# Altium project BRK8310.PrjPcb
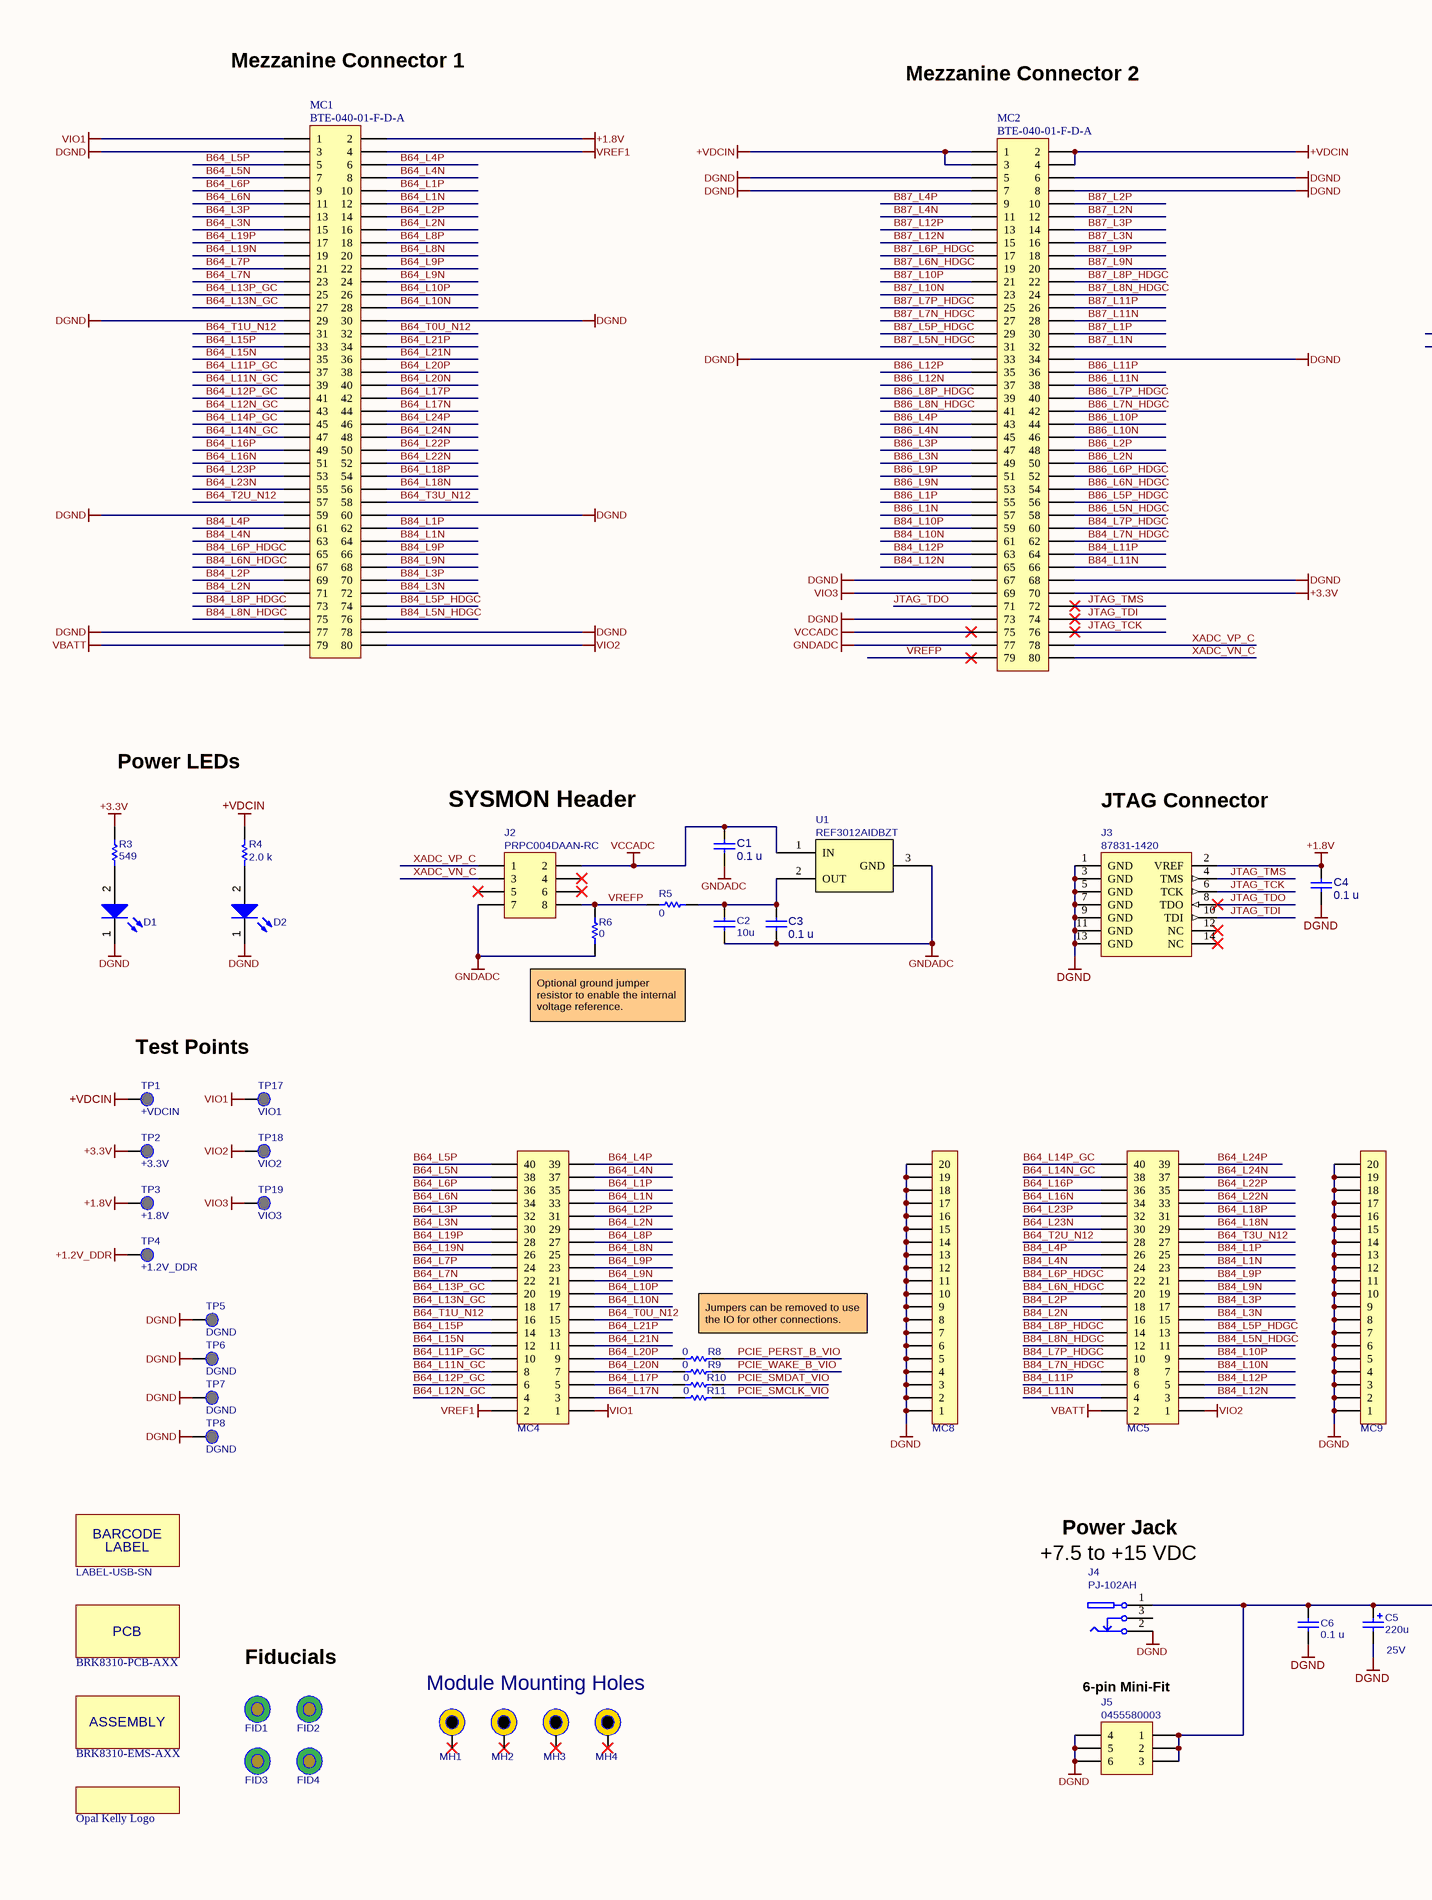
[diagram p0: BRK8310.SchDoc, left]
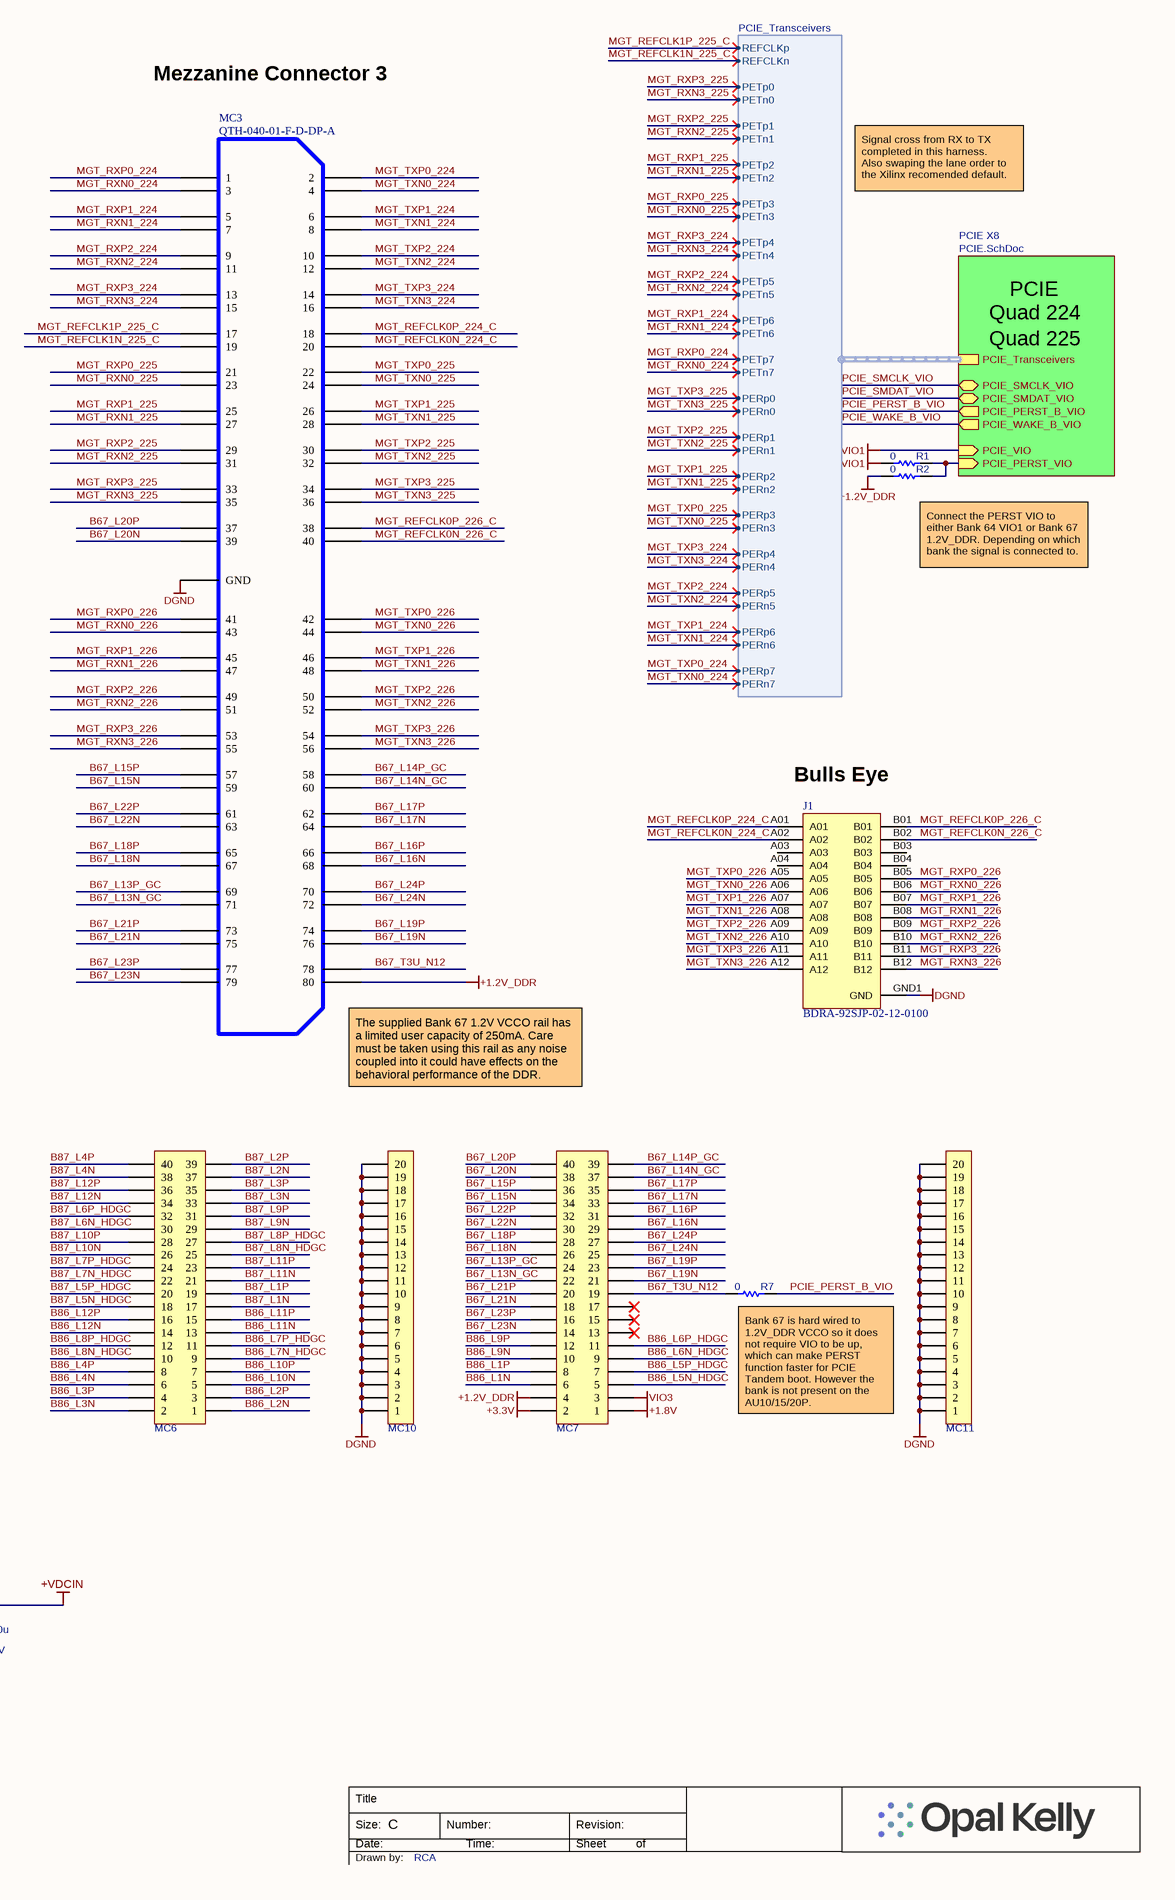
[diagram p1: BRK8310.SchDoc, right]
BOM_Revision: 01; Part_Number: BRK8310; PCB_Revision: A
2 sheets, 122 parts. Net scope: hierarchical (ports join the sheet entries above them; power ports are global).
Board file: BRK8310.PcbDoc
Sheets:
  BRK8310.SchDoc
    PCIE X8 = PCIE.SchDoc

## Sheet BRK8310.SchDoc: BRK8310 PCB
size C; Author: Ray Anderson; Organization: Opal Kelly; Address1: 13500 SW 72nd Ave, STE 100; Address2: Portland, OR 97223; Address3: 217.391.3724; Address4: http://www.opalkelly.com; DocumentNumber: 1; Revision: 1; SheetNumber: 1; SheetTotal: 2

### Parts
*  Opal Kelly Logo  [okLogo-23x5-2021]
ASSY1  BRK8310-EMS-AXX  (mechanical)
C1  value 0.1 u  [CAPC1005X06A]  (hidden comment: C0402C104K8PACTU)
C2  value 10u  [CAPC1005X06A]  (hidden comment: GRM155C80J106ME11D)
C3  value 0.1 u  [CAPC1005X06A]  (hidden comment: C0402C104K8PACTU)
C4  value 0.1 u  [CAPC1005X06A]  (hidden comment: C0402C104K8PACTU)
C5  value 220u  Voltage: 25V  [CAPAE9083X70N]  (hidden comment: EEE-FK1E221P)
C6  value 0.1 u  [CAPC1005X06A]  (hidden comment: TMK105BJ104KV-F)
D1  +3.3VDD  [CD1608-0603-PIN1-CATHODE]  (value not drawn)
D2  +VDC  [CD1608-0603-PIN1-CATHODE]  (value not drawn)
FID1  FIDUCIAL  [FID1MM/2MM-SS]  (value not drawn)
FID2  FIDUCIAL  [FID1MM/2MM-SS]  (value not drawn)
FID3  FIDUCIAL  [FID1MM/2MM-SS]  (value not drawn)
FID4  FIDUCIAL  [FID1MM/2MM-SS]  (value not drawn)
J1  BDRA-92SJP-02-12-0100  [SAMTEC_BDRA-92SJP-02-12-0100]
J2  PRPC004DAAN-RC  [HDR2X4]
J3  87831-1420  [XILINX-JTAG]
J4  PJ-102AH  [CUI-PJ102A]
J5  0455580003  [0455580003]
LABEL1  LABEL-USB-SN  (mechanical)
MC1  BTE-040-01-F-D-A  [BTE-040]
MC2  BTE-040-01-F-D-A  [BTE-040]
MC3  QTH-040-01-F-D-DP-A  [QTH-040-01-X-D-DP-A]
MC4  0877584016  [HDR2X20-2MM]  (value not drawn)
MC5  0877584016  [HDR2X20-2MM]  (value not drawn)
MC6  0877584016  [HDR2X20-2MM]  (value not drawn)
MC7  0877584016  [HDR2X20-2MM]  (value not drawn)
MC8  Header, 20-Pin, Single Row  [HDR1X20-2MM]  (value not drawn)
MC9  Header, 20-Pin, Single Row  [HDR1X20-2MM]  (value not drawn)
MC10  Header, 20-Pin, Single Row  [HDR1X20-2MM]  (value not drawn)
MC11  Header, 20-Pin, Single Row  [HDR1X20-2MM]  (value not drawn)
MH1  MTG  [MTG-3.2/6.5-PTH]  (value not drawn)
MH2  MTG  [MTG-3.2/6.5-PTH]  (value not drawn)
MH3  MTG  [MTG-3.2/6.5-PTH]  (value not drawn)
MH4  MTG  [MTG-3.2/6.5-PTH]  (value not drawn)
PCB1  BRK8310-PCB-AXX  (mechanical)
R1  value 0  [RESC1608N]  (hidden comment: CRCW06030000Z0EA)
R2  value 0  [RESC1608N]  (hidden comment: CRCW06030000Z0EA)
R3  value 549  [RESC1005X06A]  (hidden comment: CRCW0402549RFKED)
R4  value 2.0 k  [RESC1005X06A]  (hidden comment: CRCW04022K00FKED)
R5  value 0  [RESC1608N]  (hidden comment: CRCW06030000Z0EA)
R6  value 0  [RESC1608N]  (hidden comment: CRCW06030000Z0EA)
R7  value 0  [RESC1608N]  (hidden comment: CRCW06030000Z0EA)
R8  value 0  [RESC1608N]  (hidden comment: CRCW06030000Z0EA)
R9  value 0  [RESC1608N]  (hidden comment: CRCW06030000Z0EA)
R10  value 0  [RESC1608N]  (hidden comment: CRCW06030000Z0EA)
R11  value 0  [RESC1608N]  (hidden comment: CRCW06030000Z0EA)
TP1  +VDCIN  [TP-PTH-65/100]
TP2  +3.3V  [TP-PTH-65/100]
TP3  +1.8V  [TP-PTH-65/100]
TP4  +1.2V_DDR  [TP-PTH-65/100]
TP5  DGND  [TP-PTH-65/100]
TP6  DGND  [TP-PTH-65/100]
TP7  DGND  [TP-PTH-65/100]
TP8  DGND  [TP-PTH-65/100]
TP17  VIO1  [TP-PTH-65/100]
TP18  VIO2  [TP-PTH-65/100]
TP19  VIO3  [TP-PTH-65/100]
U1  REF3012AIDBZT  [SOT23-95P240X110]

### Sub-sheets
PCIE X8 = PCIE.SchDoc: PCIE_Transceivers (harness PCIE_Transceivers), PCIE_SMCLK_VIO (bidir), PCIE_WAKE_B_VIO (out), PCIE_SMDAT_VIO (bidir), PCIE_PERST_B_VIO (out), PCIE_VIO (in), PCIE_PERST_VIO (in)

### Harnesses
PCIE_Transceivers: PETn3, PETp3, PERn3, PERp3, PETn2, PETp2, PERn2, PERp2, PETn1, PETp1, PERn1, PERp1, PETn0, PETp0, PERn0, PERp0, PETn4, PETp4, PERn4, PERp4, PETn5, PETp5, PERn5, PERp5, PETn6, PETp6, PERn6, PERp6, PETn7, PETp7, PERn7, PERp7, REFCLKn, REFCLKp

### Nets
+1.2V_DDR: MC3.80 MC7.4 R2.2 TP4.1(PIN)
+1.8V: C4.1 J3.2(VREF) MC1.2 MC7.1 TP3.1(PIN)
+3.3V: MC2.70 MC7.2 R3.2 TP2.1(PIN)
+VDCIN: C5.1 C6.2 J4.1 J5.1 J5.2 J5.3 MC2.1 MC2.2 MC2.3 MC2.4 R4.2 TP1.1(PIN)
DGND: C4.2 C5.2 C6.1 D1.1(K) D2.1(K) J1.GND1(GND) J3.1(GND) J3.3(GND) J3.5(GND) J3.7(GND) J3.9(GND) J3.11(GND) J3.13(GND) J4.2 J5.4 J5.5 J5.6 MC1.3 MC1.29 MC1.30 MC1.59 MC1.60 MC1.77 MC1.78 MC2.5 MC2.6 MC2.7 MC2.8 MC2.33 MC2.34 MC2.67 MC2.68 MC2.73 MC3.0(GND) MC8.1 MC8.2 MC8.3 MC8.4 MC8.5 MC8.6 MC8.7 MC8.8 MC8.9 MC8.10 MC8.11 MC8.12 MC8.13 MC8.14 MC8.15 MC8.16 MC8.17 MC8.18 MC8.19 MC8.20 MC9.1 MC9.2 MC9.3 MC9.4 MC9.5 MC9.6 MC9.7 MC9.8 MC9.9 MC9.10 MC9.11 MC9.12 MC9.13 MC9.14 MC9.15 MC9.16 MC9.17 MC9.18 MC9.19 MC9.20 MC10.1 MC10.2 MC10.3 MC10.4 MC10.5 MC10.6 MC10.7 MC10.8 MC10.9 MC10.10 MC10.11 MC10.12 MC10.13 MC10.14 MC10.15 MC10.16 MC10.17 MC10.18 MC10.19 MC10.20 MC11.1 MC11.2 MC11.3 MC11.4 MC11.5 MC11.6 MC11.7 MC11.8 MC11.9 MC11.10 MC11.11 MC11.12 MC11.13 MC11.14 MC11.15 MC11.16 MC11.17 MC11.18 MC11.19 MC11.20 TP5.1(PIN) TP6.1(PIN) TP7.1(PIN) TP8.1(PIN)
GNDADC: C1.2 C2.1 C3.2 J2.7 MC2.77 R6.1 U1.3(GND)
VBATT: MC1.79 MC5.2
VCCADC: C1.1 J2.2 MC2.75 U1.1(IN)
VIO1: MC1.1 MC4.1 R1.2 TP17.1(PIN) ; sheet PCIE X8/PCIE_VIO
VIO2: MC1.80 MC5.1 TP18.1(PIN)
VIO3: MC2.69 MC7.3 TP19.1(PIN)
VREF1: MC1.4 MC4.2
B64_L1N: MC1.12 MC4.33
B64_L1P: MC1.10 MC4.35
B64_L2N: MC1.16 MC4.29
B64_L2P: MC1.14 MC4.31
B64_L3N: MC1.15 MC4.30
B64_L3P: MC1.13 MC4.32
B64_L4N: MC1.8 MC4.37
B64_L4P: MC1.6 MC4.39
B64_L5N: MC1.7 MC4.38
B64_L5P: MC1.5 MC4.40
B64_L6N: MC1.11 MC4.34
B64_L6P: MC1.9 MC4.36
B64_L7N: MC1.23 MC4.22
B64_L7P: MC1.21 MC4.24
B64_L8N: MC1.20 MC4.25
B64_L8P: MC1.18 MC4.27
B64_L9N: MC1.24 MC4.21
B64_L9P: MC1.22 MC4.23
B64_L10N: MC1.28 MC4.17
B64_L10P: MC1.26 MC4.19
B64_L11N_GC: MC1.39 MC4.8
B64_L11P_GC: MC1.37 MC4.10
B64_L12N_GC: MC1.43 MC4.4
B64_L12P_GC: MC1.41 MC4.6
B64_L13N_GC: MC1.27 MC4.18
B64_L13P_GC: MC1.25 MC4.20
B64_L14N_GC: MC1.47 MC5.38
B64_L14P_GC: MC1.45 MC5.40
B64_L15N: MC1.35 MC4.12
B64_L15P: MC1.33 MC4.14
B64_L16N: MC1.51 MC5.34
B64_L16P: MC1.49 MC5.36
B64_L17N: MC1.44 MC4.3 R11.2
B64_L17P: MC1.42 MC4.5 R10.2
B64_L18N: MC1.56 MC5.29
B64_L18P: MC1.54 MC5.31
B64_L19N: MC1.19 MC4.26
B64_L19P: MC1.17 MC4.28
B64_L20N: MC1.40 MC4.7 R9.2
B64_L20P: MC1.38 MC4.9 R8.2
B64_L21N: MC1.36 MC4.11
B64_L21P: MC1.34 MC4.13
B64_L22N: MC1.52 MC5.33
B64_L22P: MC1.50 MC5.35
B64_L23N: MC1.55 MC5.30
B64_L23P: MC1.53 MC5.32
B64_L24N: MC1.48 MC5.37
B64_L24P: MC1.46 MC5.39
B64_T0U_N12: MC1.32 MC4.15
B64_T1U_N12: MC1.31 MC4.16
B64_T2U_N12: MC1.57 MC5.28
B64_T3U_N12: MC1.58 MC5.27
B67_L13N_GC: MC3.71 MC7.22
B67_L13P_GC: MC3.69 MC7.24
B67_L14N_GC: MC3.60 MC7.37
B67_L14P_GC: MC3.58 MC7.39
B67_L15N: MC3.59 MC7.34
B67_L15P: MC3.57 MC7.36
B67_L16N: MC3.68 MC7.29
B67_L16P: MC3.66 MC7.31
B67_L17N: MC3.64 MC7.33
B67_L17P: MC3.62 MC7.35
B67_L18N: MC3.67 MC7.26
B67_L18P: MC3.65 MC7.28
B67_L19N: MC3.76 MC7.21
B67_L19P: MC3.74 MC7.23
B67_L20N: MC3.39 MC7.38
B67_L20P: MC3.37 MC7.40
B67_L21N: MC3.75 MC7.18
B67_L21P: MC3.73 MC7.20
B67_L22N: MC3.63 MC7.30
B67_L22P: MC3.61 MC7.32
B67_L23N: MC3.79 MC7.14
B67_L23P: MC3.77 MC7.16
B67_L24N: MC3.72 MC7.25
B67_L24P: MC3.70 MC7.27
B67_T3U_N12: MC3.78 MC7.19 R7.2
B84_L1N: MC1.64 MC5.23
B84_L1P: MC1.62 MC5.25
B84_L2N: MC1.71 MC5.16
B84_L2P: MC1.69 MC5.18
B84_L3N: MC1.72 MC5.15
B84_L3P: MC1.70 MC5.17
B84_L4N: MC1.63 MC5.24
B84_L4P: MC1.61 MC5.26
B84_L5N_HDGC: MC1.76 MC5.11
B84_L5P_HDGC: MC1.74 MC5.13
B84_L6N_HDGC: MC1.67 MC5.20
B84_L6P_HDGC: MC1.65 MC5.22
B84_L7N_HDGC: MC2.62 MC5.8
B84_L7P_HDGC: MC2.60 MC5.10
B84_L8N_HDGC: MC1.75 MC5.12
B84_L8P_HDGC: MC1.73 MC5.14
B84_L9N: MC1.68 MC5.19
B84_L9P: MC1.66 MC5.21
B84_L10N: MC2.61 MC5.7
B84_L10P: MC2.59 MC5.9
B84_L11N: MC2.66 MC5.4
B84_L11P: MC2.64 MC5.6
B84_L12N: MC2.65 MC5.3
B84_L12P: MC2.63 MC5.5
B86_L1N: MC2.57 MC7.6
B86_L1P: MC2.55 MC7.8
B86_L2N: MC2.50 MC6.1
B86_L2P: MC2.48 MC6.3
B86_L3N: MC2.49 MC6.2
B86_L3P: MC2.47 MC6.4
B86_L4N: MC2.45 MC6.6
B86_L4P: MC2.43 MC6.8
B86_L5N_HDGC: MC2.58 MC7.5
B86_L5P_HDGC: MC2.56 MC7.7
B86_L6N_HDGC: MC2.54 MC7.9
B86_L6P_HDGC: MC2.52 MC7.11
B86_L7N_HDGC: MC2.42 MC6.9
B86_L7P_HDGC: MC2.40 MC6.11
B86_L8N_HDGC: MC2.41 MC6.10
B86_L8P_HDGC: MC2.39 MC6.12
B86_L9N: MC2.53 MC7.10
B86_L9P: MC2.51 MC7.12
B86_L10N: MC2.46 MC6.5
B86_L10P: MC2.44 MC6.7
B86_L11N: MC2.38 MC6.13
B86_L11P: MC2.36 MC6.15
B86_L12N: MC2.37 MC6.14
B86_L12P: MC2.35 MC6.16
B87_L1N: MC2.32 MC6.17
B87_L1P: MC2.30 MC6.19
B87_L2N: MC2.12 MC6.37
B87_L2P: MC2.10 MC6.39
B87_L3N: MC2.16 MC6.33
B87_L3P: MC2.14 MC6.35
B87_L4N: MC2.11 MC6.38
B87_L4P: MC2.9 MC6.40
B87_L5N_HDGC: MC2.31 MC6.18
B87_L5P_HDGC: MC2.29 MC6.20
B87_L6N_HDGC: MC2.19 MC6.30
B87_L6P_HDGC: MC2.17 MC6.32
B87_L7N_HDGC: MC2.27 MC6.22
B87_L7P_HDGC: MC2.25 MC6.24
B87_L8N_HDGC: MC2.24 MC6.25
B87_L8P_HDGC: MC2.22 MC6.27
B87_L9N: MC2.20 MC6.29
B87_L9P: MC2.18 MC6.31
B87_L10N: MC2.23 MC6.26
B87_L10P: MC2.21 MC6.28
B87_L11N: MC2.28 MC6.21
B87_L11P: MC2.26 MC6.23
B87_L12N: MC2.15 MC6.34
B87_L12P: MC2.13 MC6.36
JTAG_TCK: J3.6(TCK) MC2.76
JTAG_TDI: J3.10(TDI) MC2.74
JTAG_TDO: J3.8(TDO) MC2.71
JTAG_TMS: J3.4(TMS) MC2.72
MGT_REFCLK0N_224_C: J1.A02 MC3.20
MGT_REFCLK0N_226_C: J1.B02 MC3.40
MGT_REFCLK0P_224_C: J1.A01 MC3.18
MGT_REFCLK0P_226_C: J1.B01 MC3.38
MGT_REFCLK1N_225_C: MC3.19 ; sheet PCIE X8/PCIE_Transceivers.REFCLKn
MGT_REFCLK1P_225_C: MC3.17 ; sheet PCIE X8/PCIE_Transceivers.REFCLKp
MGT_RXN0_224: MC3.3 ; sheet PCIE X8/PCIE_Transceivers.PETn7
MGT_RXN0_225: MC3.23 ; sheet PCIE X8/PCIE_Transceivers.PETn3
MGT_RXN0_226: J1.B06 MC3.43
MGT_RXN1_224: MC3.7 ; sheet PCIE X8/PCIE_Transceivers.PETn6
MGT_RXN1_225: MC3.27 ; sheet PCIE X8/PCIE_Transceivers.PETn2
MGT_RXN1_226: J1.B08 MC3.47
MGT_RXN2_224: MC3.11 ; sheet PCIE X8/PCIE_Transceivers.PETn5
MGT_RXN2_225: MC3.31 ; sheet PCIE X8/PCIE_Transceivers.PETn1
MGT_RXN2_226: J1.B10 MC3.51
MGT_RXN3_224: MC3.15 ; sheet PCIE X8/PCIE_Transceivers.PETn4
MGT_RXN3_225: MC3.35 ; sheet PCIE X8/PCIE_Transceivers.PETn0
MGT_RXN3_226: J1.B12 MC3.55
MGT_RXP0_224: MC3.1 ; sheet PCIE X8/PCIE_Transceivers.PETp7
MGT_RXP0_225: MC3.21 ; sheet PCIE X8/PCIE_Transceivers.PETp3
MGT_RXP0_226: J1.B05 MC3.41
MGT_RXP1_224: MC3.5 ; sheet PCIE X8/PCIE_Transceivers.PETp6
MGT_RXP1_225: MC3.25 ; sheet PCIE X8/PCIE_Transceivers.PETp2
MGT_RXP1_226: J1.B07 MC3.45
MGT_RXP2_224: MC3.9 ; sheet PCIE X8/PCIE_Transceivers.PETp5
MGT_RXP2_225: MC3.29 ; sheet PCIE X8/PCIE_Transceivers.PETp1
MGT_RXP2_226: J1.B09 MC3.49
MGT_RXP3_224: MC3.13 ; sheet PCIE X8/PCIE_Transceivers.PETp4
MGT_RXP3_225: MC3.33 ; sheet PCIE X8/PCIE_Transceivers.PETp0
MGT_RXP3_226: J1.B11 MC3.53
MGT_TXN0_224: MC3.4 ; sheet PCIE X8/PCIE_Transceivers.PERn7
MGT_TXN0_225: MC3.24 ; sheet PCIE X8/PCIE_Transceivers.PERn3
MGT_TXN0_226: J1.A06 MC3.44
MGT_TXN1_224: MC3.8 ; sheet PCIE X8/PCIE_Transceivers.PERn6
MGT_TXN1_225: MC3.28 ; sheet PCIE X8/PCIE_Transceivers.PERn2
MGT_TXN1_226: J1.A08 MC3.48
MGT_TXN2_224: MC3.12 ; sheet PCIE X8/PCIE_Transceivers.PERn5
MGT_TXN2_225: MC3.32 ; sheet PCIE X8/PCIE_Transceivers.PERn1
MGT_TXN2_226: J1.A10 MC3.52
MGT_TXN3_224: MC3.16 ; sheet PCIE X8/PCIE_Transceivers.PERn4
MGT_TXN3_225: MC3.36 ; sheet PCIE X8/PCIE_Transceivers.PERn0
MGT_TXN3_226: J1.A12 MC3.56
MGT_TXP0_224: MC3.2 ; sheet PCIE X8/PCIE_Transceivers.PERp7
MGT_TXP0_225: MC3.22 ; sheet PCIE X8/PCIE_Transceivers.PERp3
MGT_TXP0_226: J1.A05 MC3.42
MGT_TXP1_224: MC3.6 ; sheet PCIE X8/PCIE_Transceivers.PERp6
MGT_TXP1_225: MC3.26 ; sheet PCIE X8/PCIE_Transceivers.PERp2
MGT_TXP1_226: J1.A07 MC3.46
MGT_TXP2_224: MC3.10 ; sheet PCIE X8/PCIE_Transceivers.PERp5
MGT_TXP2_225: MC3.30 ; sheet PCIE X8/PCIE_Transceivers.PERp1
MGT_TXP2_226: J1.A09 MC3.50
MGT_TXP3_224: MC3.14 ; sheet PCIE X8/PCIE_Transceivers.PERp4
MGT_TXP3_225: MC3.34 ; sheet PCIE X8/PCIE_Transceivers.PERp0
MGT_TXP3_226: J1.A11 MC3.54
PCIE_PERST_B_VIO: R7.1 R8.1 ; sheet PCIE X8/PCIE_PERST_B_VIO
PCIE_SMCLK_VIO: R11.1 ; sheet PCIE X8/PCIE_SMCLK_VIO
PCIE_SMDAT_VIO: R10.1 ; sheet PCIE X8/PCIE_SMDAT_VIO
PCIE_WAKE_B_VIO: R9.1 ; sheet PCIE X8/PCIE_WAKE_B_VIO
VREFP: J2.8 MC2.79 R5.2 R6.2
XADC_VN_C: J2.3 MC2.80
XADC_VP_C: J2.1 MC2.78
NetC2_2: C2.2 C3.1 R5.1 U1.2(OUT)
NetC11_2: R1.1 R2.1 ; sheet PCIE X8/PCIE_PERST_VIO
NetD1_2: D1.2(A) R3.1
NetD2_2: D2.2(A) R4.1

Not connected (* = marked no-connect by the designer): J1 A03 A04 B03 B04; J2 4* 5* 6*; J3 12(NC)* 14(NC)*; J4 3; MC7 13* 15* 17*; MH1 1*; MH2 1*; MH3 1*; MH4 1*

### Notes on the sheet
- Mezzanine Connector 1
- Mezzanine Connector 2
- Mezzanine Connector 3
- Signal cross from RX to TX completed in this harness.
  Also swaping the lane order to the Xilinx recomended default.
- PCIE
- Quad 224
- Quad 225
- Connect the PERST VIO to either Bank 64 VIO1 or Bank 67 1.2V_DDR. Depending on which bank the signal is connected to.
- Power LEDs
- SYSMON Header
- JTAG Connector
- (near J1) Bulls Eye
- (near R6) Optional ground jumper resistor to enable the internal voltage reference.
- Test Points
- (near MC3) The supplied Bank 67 1.2V VCCO rail has a limited user capacity of 250mA. Care must be taken using this rail as any noise coupled into it could have effects on the behavioral performance of the DDR.
- Jumpers can be removed to use the IO for other connections.
- (near R7) Bank 67 is hard wired to 1.2V_DDR VCCO so it does not require VIO to be up, which can make PERST function faster for PCIE Tandem boot. However the bank is not present on the AU10/15/20P.
- Power Jack
- (near J4) +7.5 to +15 VDC
- Fiducials
- Module Mounting Holes
- 6-pin Mini-Fit
- Title
- Size:
- Date:
- Drawn by:
- C
- RCA
- Number:
- Time:
- Revision:
- Sheet
- of

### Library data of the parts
* = OKLOGO: partnumber: ALIGNI_IGNORE
ASSY1 = 002352: BRK8310 PCB assembly; Partnumber: 002352; Manufacturer: PCB Assembly Cost
C1 C3 C4 = 000070: Ceramic capacitor; Manufacturer: Kemet; partnumber: 000070; Description 2: SM-0402, 10%, 10v; ValueFloat: 1E-7; Tolerance (%): 10
C2 = 001983: Ceramic capacitor; Partnumber: 001983; Manufacturer: Murata; ValueFloat: 1E-5; Tolerance (%): 20; Description 2: 0402, 6.3V
C5 = 001532: Polarized; Partnumber: 001532; manufacturer: Panasonic; ValueFloat: 0.00022; id: 155442; inventory_price: 0.2; x_tolerance: 20; x_voltage-rating: 25
C6 = 001073: Ceramic capacitor; Manufacturer: Taiyo Yuden; partnumber: 001073; Description 2: 0402, 25V; ValueFloat: 1E-7; Tolerance (%): 10; Voltage: 25V
D1 D2 = 001433: LED; Manufacturer: Dialight; Manufacturer_PN: 598-8070-107F; partnumber: 001433; Description 2: SM-0603, green; x_lifecycle_status: Production
FID1-FID4 = FIDUCIAL: PCB fiducial
J1 = BDRA-92SJP-02-12-0100: MF: Samtec
J2 = 001193: Partnumber: 001193; manufacturer: Sullins Electronics Corp.
J3 = 000541: 2mm header, shrouded; Manufacturer: Molex; partnumber: 000541; Description 2: Dual-row, 14-pos, Xilinx JTAG compatible
J4 = 000356: DC power connector - high current; Manufacturer: CUI Inc.; partnumber: 000356; Description 2: 2.1mm / 5.5mm
J5 = 001950: Partnumber: 001950; manufacturer: Molex
LABEL1 = 000605: Barcode serial number labels for USB devices; Manufacturer: Techiant; partnumber: 000605; Description 2: 4-digit, all four, alphanumeric, case insensitive; x_lifecycle_status: Production
MC1 MC2 = 000059: 0.8mm high-density header; Partnumber: 000059; Manufacturer: Samtec; Description 2: 80-pin, Gold flash, Mated height: 5.00mm (0.197 inch)
MC3 = 002313: 0.5mm hi-speed, high-density header (female); Partnumber: 002313; Manufacturer: Samtec; Description 2: 80-pin, ground protection in middle
MC4-MC7 = 000583: Partnumber: 000583; manufacturer: Molex; id: 9990; inventory_price: 1.03
MC8-MC11 = 001334: PartNumber: 001334; manufacturer: 3M; manufacturer_pn: 951120-8622-AR; id: 98023; inventory_price: 0.924
MH1-MH4 = MTG: Mounting hole
PCB1 = 002353: PCB for BRK8310; Partnumber: 002353; Manufacturer: Generic PCB Manufacturer
R1 R2 R5-R11 = 000411: Zero-ohm resistor; Manufacturer: Vishay; partnumber: 000411; Description 2: SM-0603, 1/10W, 20 mOhm max, 2.0 A max
R3 = 001038: Thick-film resistor; Manufacturer: Vishay; partnumber: 001038; Description 2: SM-0402, 1%, 1/16W; Tolerance (%): 1
R4 = 001162: Thick-film resistor; Manufacturer: Vishay; partnumber: 001162; Description 2: SM-0402, 1%, 1/16W; ValueFloat: 2000; Tolerance (%): 1
TP1-TP8 TP17-TP19 = TP-PTH-65/100: Test point, plated through-hole, 65/100mil
U1 = 000728: 1.25V Voltage Reference; Manufacturer: Texas Instruments; partnumber: 000728; Description 2: 50ppm/C, 50uA

## Sheet PCIE.SchDoc: BRK8310 - PCIE
size C; Author: Ray Anderson; Organization: Opal Kelly; Address1: 13500 SW 72nd Ave, STE 100; Address2: Portland, OR 97223; Address3: 217.391.3724; Address4: http://www.opalkelly.com; DocumentNumber: 2; Revision: 1; SheetNumber: 2; SheetTotal: 2
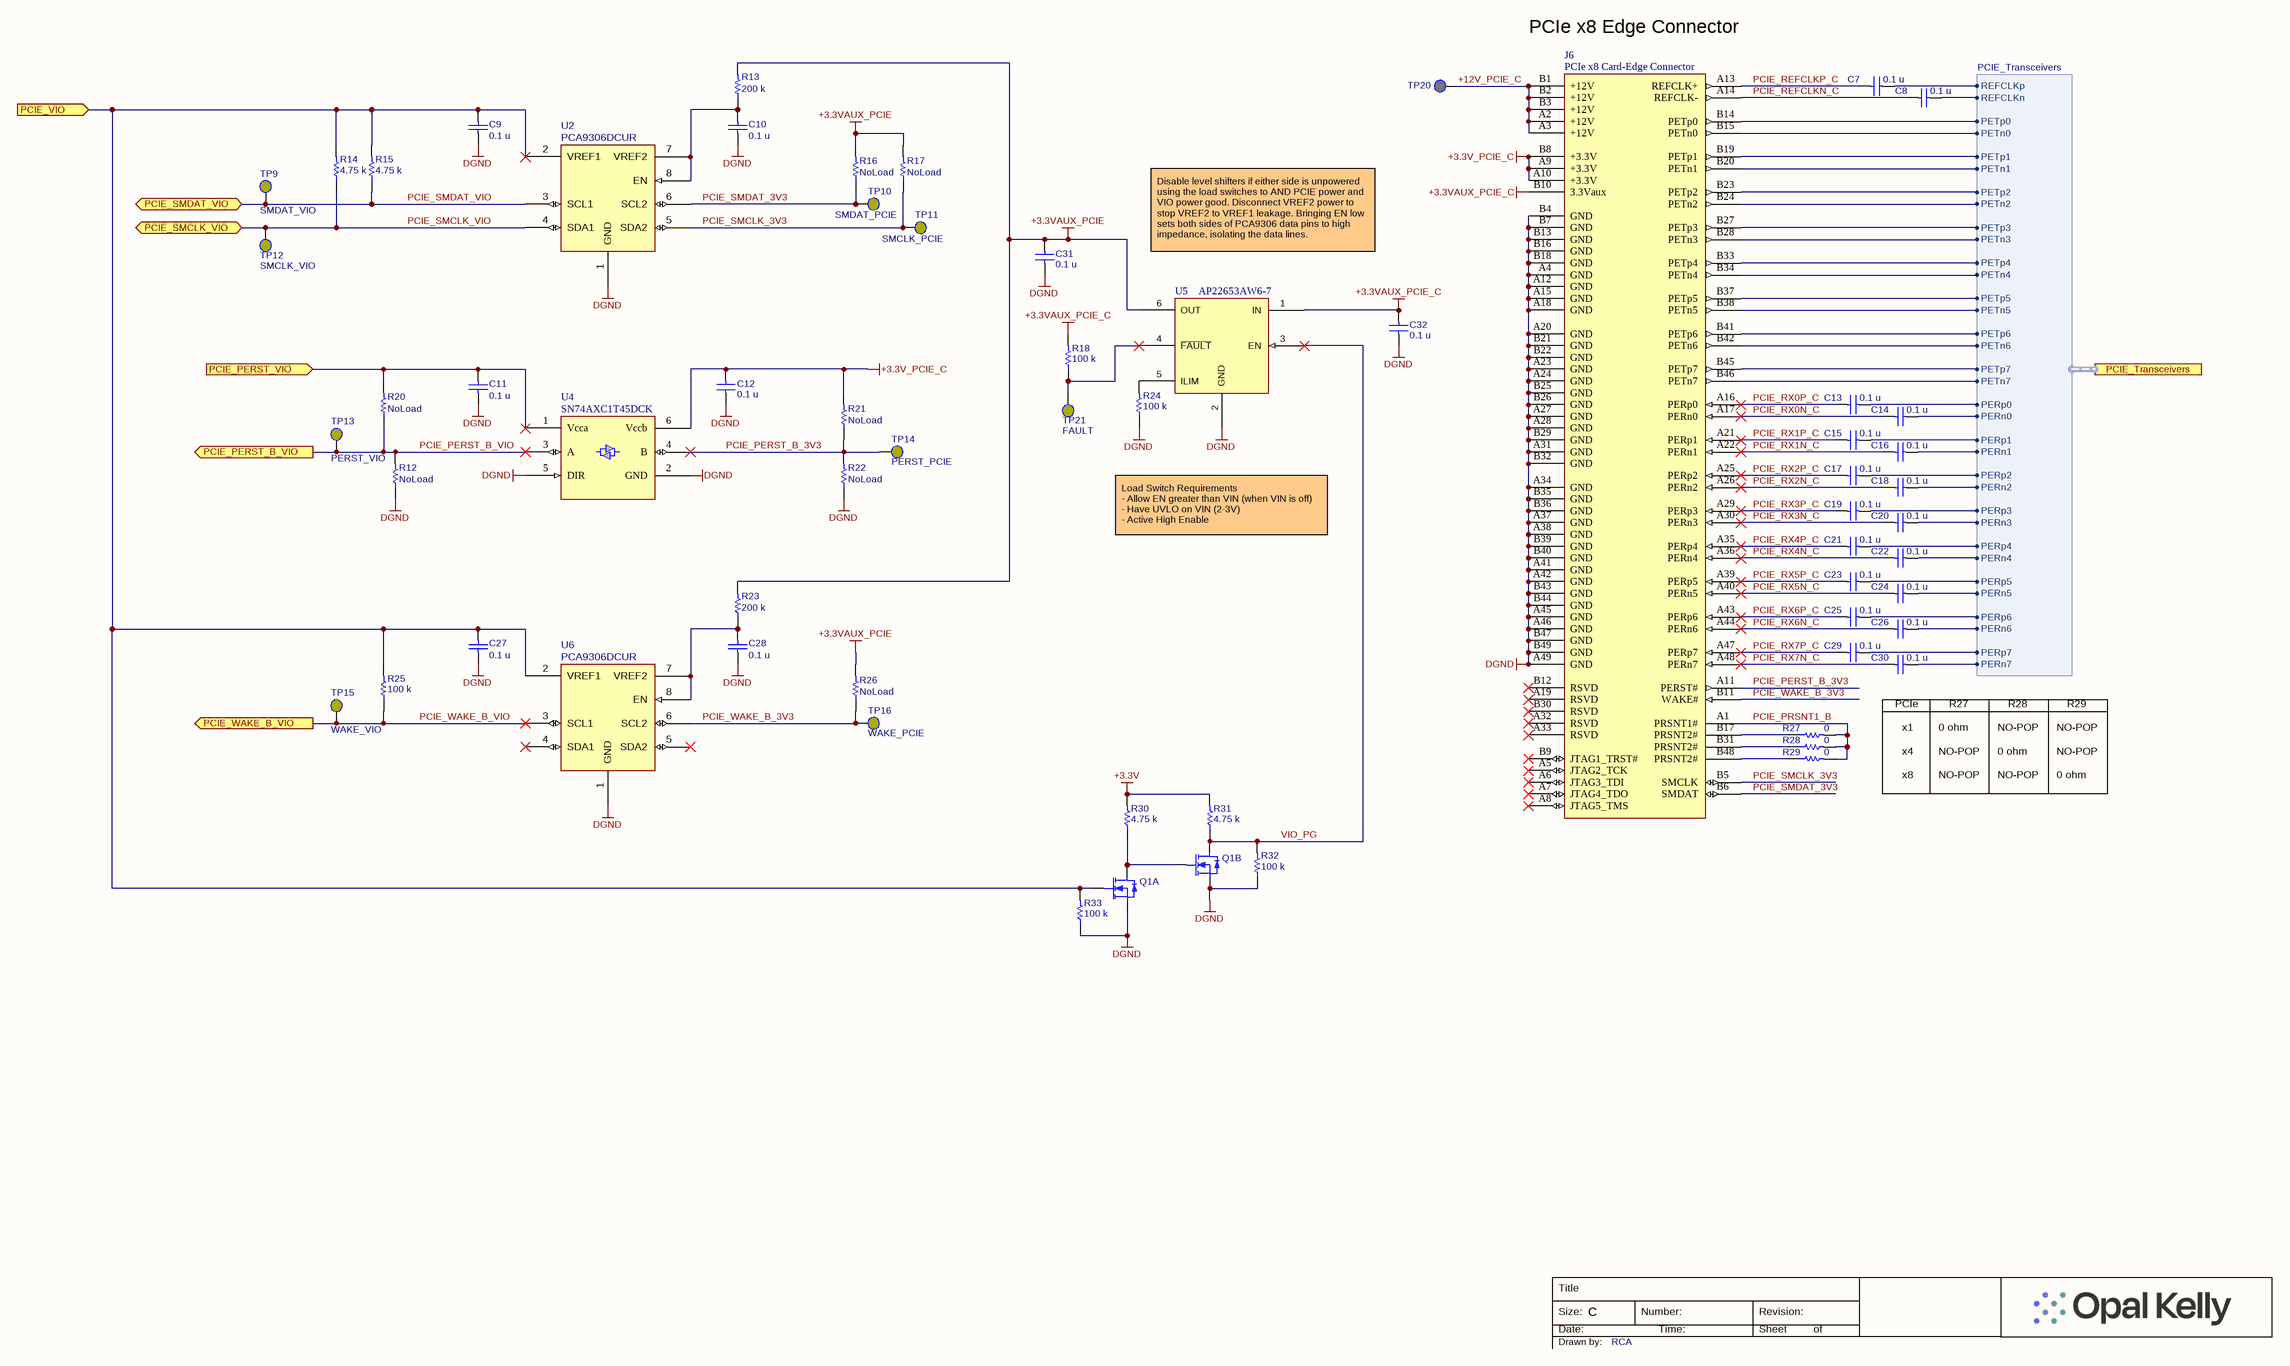
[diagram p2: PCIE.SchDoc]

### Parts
C7  value 0.1 u  [CAPC1005X06A]  (hidden comment: C0402C104K8PACTU)
C8  value 0.1 u  [CAPC1005X06A]  (hidden comment: C0402C104K8PACTU)
C9  value 0.1 u  [CAPC1005X06A]  (hidden comment: C0402C104K8PACTU)
C10  value 0.1 u  [CAPC1005X06A]  (hidden comment: C0402C104K8PACTU)
C11  value 0.1 u  [CAPC1005X06A]  (hidden comment: C0402C104K8PACTU)
C12  value 0.1 u  [CAPC1005X06A]  (hidden comment: C0402C104K8PACTU)
C13  value 0.1 u  [CAPC1005X06A]  (hidden comment: C0402C104K8PACTU)
C14  value 0.1 u  [CAPC1005X06A]  (hidden comment: C0402C104K8PACTU)
C15  value 0.1 u  [CAPC1005X06A]  (hidden comment: C0402C104K8PACTU)
C16  value 0.1 u  [CAPC1005X06A]  (hidden comment: C0402C104K8PACTU)
C17  value 0.1 u  [CAPC1005X06A]  (hidden comment: C0402C104K8PACTU)
C18  value 0.1 u  [CAPC1005X06A]  (hidden comment: C0402C104K8PACTU)
C19  value 0.1 u  [CAPC1005X06A]  (hidden comment: C0402C104K8PACTU)
C20  value 0.1 u  [CAPC1005X06A]  (hidden comment: C0402C104K8PACTU)
C21  value 0.1 u  [CAPC1005X06A]  (hidden comment: C0402C104K8PACTU)
C22  value 0.1 u  [CAPC1005X06A]  (hidden comment: C0402C104K8PACTU)
C23  value 0.1 u  [CAPC1005X06A]  (hidden comment: C0402C104K8PACTU)
C24  value 0.1 u  [CAPC1005X06A]  (hidden comment: C0402C104K8PACTU)
C25  value 0.1 u  [CAPC1005X06A]  (hidden comment: C0402C104K8PACTU)
C26  value 0.1 u  [CAPC1005X06A]  (hidden comment: C0402C104K8PACTU)
C27  value 0.1 u  [CAPC1005X06A]  (hidden comment: C0402C104K8PACTU)
C28  value 0.1 u  [CAPC1005X06A]  (hidden comment: C0402C104K8PACTU)
C29  value 0.1 u  [CAPC1005X06A]  (hidden comment: C0402C104K8PACTU)
C30  value 0.1 u  [CAPC1005X06A]  (hidden comment: C0402C104K8PACTU)
C31  value 0.1 u  [CAPC1005X06A]  (hidden comment: C0402C104K8PACTU)
C32  value 0.1 u  [CAPC1005X06A]  (hidden comment: C0402C104K8PACTU)
J6  PCIe x8 Card-Edge Connector  [PCIEx8-FULL-HEIGHT]
Q1  SI1922EDH-T1-GE3  [SOT363-6N]  (value not drawn)  (parts A,B of 2)
R12  NoLoad  [RESC1005X06A]
R13  value 200 k  [RESC1005X06A]  (hidden comment: CRCW0402200KFKED)
R14  value 4.75 k  [RESC1005X06A]  (hidden comment: CRCW04024K75FKED)
R15  value 4.75 k  [RESC1005X06A]  (hidden comment: CRCW04024K75FKED)
R16  NoLoad  [RESC1005X06A]
R17  NoLoad  [RESC1005X06A]
R18  value 100 k  [RESC1005X06A]  (hidden comment: CRCW0402100KFKED)
R20  NoLoad  [RESC1005X06A]
R21  NoLoad  [RESC1005X06A]
R22  NoLoad  [RESC1005X06A]
R23  value 200 k  [RESC1005X06A]  (hidden comment: CRCW0402200KFKED)
R24  value 100 k  [RESC1005X06A]  (hidden comment: CRCW0402100KFKED)
R25  value 100 k  [RESC1005X06A]  (hidden comment: CRCW0402100KFKED)
R26  NoLoad  [RESC1005X06A]
R27  value 0  [RESC1005X06A]  (hidden comment: CRCW04020000Z0ED)
R28  value 0  [RESC1005X06A]  (hidden comment: CRCW04020000Z0ED)
R29  value 0  [RESC1005X06A]  (hidden comment: CRCW04020000Z0ED)
R30  value 4.75 k  [RESC1005X06A]  (hidden comment: CRCW04024K75FKED)
R31  value 4.75 k  [RESC1005X06A]  (hidden comment: CRCW04024K75FKED)
R32  value 100 k  [RESC1005X06A]  (hidden comment: CRCW0402100KFKED)
R33  value 100 k  [RESC1005X06A]  (hidden comment: CRCW0402100KFKED)
TP9  SMDAT_VIO  [TP-SMD40]
TP10  SMDAT_PCIE  [TP-SMD40]
TP11  SMCLK_PCIE  [TP-SMD40]
TP12  SMCLK_VIO  [TP-SMD40]
TP13  PERST_VIO  [TP-SMD40]
TP14  PERST_PCIE  [TP-SMD40]
TP15  WAKE_VIO  [TP-SMD40]
TP16  WAKE_PCIE  [TP-SMD40]
TP20  +12V_PCIE_C  [TP-PTH-65/100]  (value not drawn)
TP21  FAULT  [TP-SMD40]
U2  PCA9306DCUR  [PCA9306DCU]
U4  SN74AXC1T45DCK  [DCK-R-PDSO-G6]
U5  AP22653AW6-7  [AP2265XW6]
U6  PCA9306DCUR  [PCA9306DCU]

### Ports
PCIE_PERST_B_VIO (out), PCIE_PERST_VIO (in), PCIE_SMCLK_VIO (bidir), PCIE_SMDAT_VIO (bidir), PCIE_Transceivers (harness PCIE_Transceivers), PCIE_VIO (in), PCIE_WAKE_B_VIO (out)

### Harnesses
PCIE_Transceivers: PETn3, PETp3, PERn3, PERp3, PETn2, PETp2, PERn2, PERp2, PETn1, PETp1, PERn1, PERp1, PETn0, PETp0, PERn0, PERp0, PETn4, PETp4, PERn4, PERp4, PETn5, PETp5, PERn5, PERp5, PETn6, PETp6, PERn6, PERp6, PETn7, PETp7, PERn7, PERp7, REFCLKn, REFCLKp

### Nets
+3.3V: R30.2 R31.2
+3.3V_PCIE_C: C12.2 J6.A9(+3.3V) J6.A10(+3.3V) J6.B8(+3.3V) R21.2 U4.6(Vccb)
+3.3VAUX_PCIE: C31.2 R13.2 R16.2 R17.2 R23.2 R26.2 U5.6(OUT)
+3.3VAUX_PCIE_C: C32.2 J6.B10(3.3Vaux) R18.2 U5.1(IN)
DGND: C9.1 C10.1 C11.1 C12.1 C27.1 C28.1 C31.1 C32.1 J6.A4(GND) J6.A12(GND) J6.A15(GND) J6.A18(GND) J6.A20(GND) J6.A23(GND) J6.A24(GND) J6.A27(GND) J6.A28(GND) J6.A31(GND) J6.A34(GND) J6.A37(GND) J6.A38(GND) J6.A41(GND) J6.A42(GND) J6.A45(GND) J6.A46(GND) J6.A49(GND) J6.B4(GND) J6.B7(GND) J6.B13(GND) J6.B16(GND) J6.B18(GND) J6.B21(GND) J6.B22(GND) J6.B25(GND) J6.B26(GND) J6.B29(GND) J6.B32(GND) J6.B35(GND) J6.B36(GND) J6.B39(GND) J6.B40(GND) J6.B43(GND) J6.B44(GND) J6.B47(GND) J6.B49(GND) Q1.1(S1) Q1.4(S2) R12.1 R22.1 R24.1 R32.1 R33.1 U2.1(GND) U4.2(GND) U4.5(DIR) U5.2(GND) U6.1(GND)
VIO1: C9.2 C27.2 Q1.2(G1) R14.2 R15.2 R25.2 R33.2 U2.2(VREF1) U6.2(VREF1) ; port PCIE_VIO
+12V_PCIE_C: J6.A2(+12V) J6.A3(+12V) J6.B1(+12V) J6.B2(+12V) J6.B3(+12V) TP20.1(PIN)
MGT_REFCLK1N_225_C: C8.2 ; port PCIE_Transceivers.REFCLKn
MGT_REFCLK1P_225_C: C7.2 ; port PCIE_Transceivers.REFCLKp
MGT_RXN0_224: J6.B46(PETn7) ; port PCIE_Transceivers.PETn7
MGT_RXN0_225: J6.B28(PETn3) ; port PCIE_Transceivers.PETn3
MGT_RXN1_224: J6.B42(PETn6) ; port PCIE_Transceivers.PETn6
MGT_RXN1_225: J6.B24(PETn2) ; port PCIE_Transceivers.PETn2
MGT_RXN2_224: J6.B38(PETn5) ; port PCIE_Transceivers.PETn5
MGT_RXN2_225: J6.B20(PETn1) ; port PCIE_Transceivers.PETn1
MGT_RXN3_224: J6.B34(PETn4) ; port PCIE_Transceivers.PETn4
MGT_RXN3_225: J6.B15(PETn0) ; port PCIE_Transceivers.PETn0
MGT_RXP0_224: J6.B45(PETp7) ; port PCIE_Transceivers.PETp7
MGT_RXP0_225: J6.B27(PETp3) ; port PCIE_Transceivers.PETp3
MGT_RXP1_224: J6.B41(PETp6) ; port PCIE_Transceivers.PETp6
MGT_RXP1_225: J6.B23(PETp2) ; port PCIE_Transceivers.PETp2
MGT_RXP2_224: J6.B37(PETp5) ; port PCIE_Transceivers.PETp5
MGT_RXP2_225: J6.B19(PETp1) ; port PCIE_Transceivers.PETp1
MGT_RXP3_224: J6.B33(PETp4) ; port PCIE_Transceivers.PETp4
MGT_RXP3_225: J6.B14(PETp0) ; port PCIE_Transceivers.PETp0
MGT_TXN0_224: C30.2 ; port PCIE_Transceivers.PERn7
MGT_TXN0_225: C20.2 ; port PCIE_Transceivers.PERn3
MGT_TXN1_224: C26.2 ; port PCIE_Transceivers.PERn6
MGT_TXN1_225: C18.2 ; port PCIE_Transceivers.PERn2
MGT_TXN2_224: C24.2 ; port PCIE_Transceivers.PERn5
MGT_TXN2_225: C16.2 ; port PCIE_Transceivers.PERn1
MGT_TXN3_224: C22.2 ; port PCIE_Transceivers.PERn4
MGT_TXN3_225: C14.2 ; port PCIE_Transceivers.PERn0
MGT_TXP0_224: C29.2 ; port PCIE_Transceivers.PERp7
MGT_TXP0_225: C19.2 ; port PCIE_Transceivers.PERp3
MGT_TXP1_224: C25.2 ; port PCIE_Transceivers.PERp6
MGT_TXP1_225: C17.2 ; port PCIE_Transceivers.PERp2
MGT_TXP2_224: C23.2 ; port PCIE_Transceivers.PERp5
MGT_TXP2_225: C15.2 ; port PCIE_Transceivers.PERp1
MGT_TXP3_224: C21.2 ; port PCIE_Transceivers.PERp4
MGT_TXP3_225: C13.2 ; port PCIE_Transceivers.PERp0
PCIE_PERST_B_3V3: J6.A11(PERST#) R21.1 R22.2 TP14.1(PIN) U4.4(B)
PCIE_PERST_B_VIO: R12.2 R20.1 TP13.1(PIN) U4.3(A) ; port PCIE_PERST_B_VIO
PCIE_PRSNT1_B: J6.A1(PRSNT1#) R27.2 R28.2 R29.2
PCIE_REFCLKN_C: C8.1 J6.A14(REFCLK-)
PCIE_REFCLKP_C: C7.1 J6.A13(REFCLK+)
PCIE_RX0N_C: C14.1 J6.A17(PERn0)
PCIE_RX0P_C: C13.1 J6.A16(PERp0)
PCIE_RX1N_C: C16.1 J6.A22(PERn1)
PCIE_RX1P_C: C15.1 J6.A21(PERp1)
PCIE_RX2N_C: C18.1 J6.A26(PERn2)
PCIE_RX2P_C: C17.1 J6.A25(PERp2)
PCIE_RX3N_C: C20.1 J6.A30(PERn3)
PCIE_RX3P_C: C19.1 J6.A29(PERp3)
PCIE_RX4N_C: C22.1 J6.A36(PERn4)
PCIE_RX4P_C: C21.1 J6.A35(PERp4)
PCIE_RX5N_C: C24.1 J6.A40(PERn5)
PCIE_RX5P_C: C23.1 J6.A39(PERp5)
PCIE_RX6N_C: C26.1 J6.A44(PERn6)
PCIE_RX6P_C: C25.1 J6.A43(PERp6)
PCIE_RX7N_C: C30.1 J6.A48(PERn7)
PCIE_RX7P_C: C29.1 J6.A47(PERp7)
PCIE_SMCLK_3V3: J6.B5(SMCLK) R17.1 TP11.1(PIN) U2.5(SDA2)
PCIE_SMCLK_VIO: R14.1 TP12.1(PIN) U2.4(SDA1) ; port PCIE_SMCLK_VIO
PCIE_SMDAT_3V3: J6.B6(SMDAT) R16.1 TP10.1(PIN) U2.6(SCL2)
PCIE_SMDAT_VIO: R15.1 TP9.1(PIN) U2.3(SCL1) ; port PCIE_SMDAT_VIO
PCIE_WAKE_B_3V3: J6.B11(WAKE#) R26.1 TP16.1(PIN) U6.6(SCL2)
PCIE_WAKE_B_VIO: R25.1 TP15.1(PIN) U6.3(SCL1) ; port PCIE_WAKE_B_VIO
VIO_PG: Q1.3(D2) R31.1 R32.2 U5.3(EN)
NetC10_2: C10.2 R13.1 U2.7(VREF2) U2.8(EN)
NetC11_2: C11.2 R20.2 U4.1(Vcca) ; port PCIE_PERST_VIO
NetC28_2: C28.2 R23.1 U6.7(VREF2) U6.8(EN)
NetJ6_B17: J6.B17(PRSNT2#) R27.1
NetJ6_B31: J6.B31(PRSNT2#) R28.1
NetJ6_B48: J6.B48(PRSNT2#) R29.1
NetQ1_5: Q1.5(G2) Q1.6(D1) R30.1
NetR18_1: R18.1 TP21.1(PIN) U5.4(~{FAULT})
NetR24_2: R24.2 U5.5(ILIM)

Not connected (* = marked no-connect by the designer): J6 A5(JTAG2_TCK)* A6(JTAG3_TDI)* A7(JTAG4_TDO)* A8(JTAG5_TMS)* A19(RSVD)* A32(RSVD)* A33(RSVD)* B9(JTAG1_TRST#)* B12(RSVD)* B30(RSVD)*; U6 4(SDA1)* 5(SDA2)*

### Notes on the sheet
- PCIe x8 Edge Connector
- Disable level shifters if either side is unpowered using the load switches to AND PCIE power and VIO power good. Disconnect VREF2 power to stop VREF2 to VREF1 leakage. Bringing EN low sets both sides of PCA9306 data pins to high impedance, isolating the data lines.
- Load Switch Requirements
  - Allow EN greater than VIN (when VIN is off)
  - Have UVLO on VIN (2-3V)
  - Active High Enable
- (near C30) PCIe
- x1
- x4
- 0 ohm
- NO-POP
- R27
- R28
- R29
- x8
- Title
- Size:
- Date:
- Drawn by:
- C
- RCA
- Number:
- Time:
- Revision:
- Sheet
- of

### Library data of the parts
C7-C32 = 001073: Partnumber: 000070; manufacturer: Kemet; ValueFloat: 1E-7; x_tolerance: 10
J6 = PCIEX8
Q1 = 002018: Partnumber: 002018; manufacturer: Vishay
R12 R16 R17 R20-R22 R26 = Resistor-NoLoad: Resistor, NoLoad; partnumber: ALIGNI_IGNORE
R13 R23 = 000964: Partnumber: 000964; manufacturer: Vishay; ValueFloat: 200000; x_tolerance: 1
R14 R15 R30 R31 = 001008: Partnumber: 001008; manufacturer: Vishay; ValueFloat: 4750; x_tolerance: 1
R18 R24 R25 R32 R33 = 001070: Thick-film resistor; Partnumber: 001070; Manufacturer: Vishay; ValueFloat: 100000; Tolerance (%): 1; Description 2: SM-0402, 1%, 1/16W
R27-R29 = 000755: Partnumber: 000755; manufacturer: Vishay; x_tolerance: 1
TP9-TP16 TP21 = TESTPOINT-SMD40: Test point, surface-mount, 40mil
TP20 = TP-PTH-65/100: as TP1 on sheet BRK8310
U2 U6 = 001474: Partnumber: 001474; manufacturer: Texas Instruments
U4 = 002140: Level Translator, 0.65V - 3.6V, Direction Control; Partnumber: 002140; Manufacturer: Texas Instruments; Description 2: Single Bit, Dual Supplies
U5 = 002224: Load Switch with Adjustable Current Limit, Latching; Partnumber: 002224; Manufacturer: Diodes Incorporated; Description 2: 3V - 5.5V, 125mA to 2665mA Limit, Fault Out

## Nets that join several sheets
+3.3V: BRK8310 (MC2.70 MC7.2 R3.2 TP2.1), PCIE (R30.2 R31.2)
DGND: BRK8310 (118 pins), PCIE (57 pins)
VIO1: BRK8310 (MC1.1 MC4.1 R1.2 TP17.1), PCIE (9 pins)
MGT_REFCLK1N_225_C: BRK8310 (MC3.19), PCIE (C8.2)
MGT_REFCLK1P_225_C: BRK8310 (MC3.17), PCIE (C7.2)
MGT_RXN0_224: BRK8310 (MC3.3), PCIE (J6.B46)
MGT_RXN0_225: BRK8310 (MC3.23), PCIE (J6.B28)
MGT_RXN1_224: BRK8310 (MC3.7), PCIE (J6.B42)
MGT_RXN1_225: BRK8310 (MC3.27), PCIE (J6.B24)
MGT_RXN2_224: BRK8310 (MC3.11), PCIE (J6.B38)
MGT_RXN2_225: BRK8310 (MC3.31), PCIE (J6.B20)
MGT_RXN3_224: BRK8310 (MC3.15), PCIE (J6.B34)
MGT_RXN3_225: BRK8310 (MC3.35), PCIE (J6.B15)
MGT_RXP0_224: BRK8310 (MC3.1), PCIE (J6.B45)
MGT_RXP0_225: BRK8310 (MC3.21), PCIE (J6.B27)
MGT_RXP1_224: BRK8310 (MC3.5), PCIE (J6.B41)
MGT_RXP1_225: BRK8310 (MC3.25), PCIE (J6.B23)
MGT_RXP2_224: BRK8310 (MC3.9), PCIE (J6.B37)
MGT_RXP2_225: BRK8310 (MC3.29), PCIE (J6.B19)
MGT_RXP3_224: BRK8310 (MC3.13), PCIE (J6.B33)
MGT_RXP3_225: BRK8310 (MC3.33), PCIE (J6.B14)
MGT_TXN0_224: BRK8310 (MC3.4), PCIE (C30.2)
MGT_TXN0_225: BRK8310 (MC3.24), PCIE (C20.2)
MGT_TXN1_224: BRK8310 (MC3.8), PCIE (C26.2)
MGT_TXN1_225: BRK8310 (MC3.28), PCIE (C18.2)
MGT_TXN2_224: BRK8310 (MC3.12), PCIE (C24.2)
MGT_TXN2_225: BRK8310 (MC3.32), PCIE (C16.2)
MGT_TXN3_224: BRK8310 (MC3.16), PCIE (C22.2)
MGT_TXN3_225: BRK8310 (MC3.36), PCIE (C14.2)
MGT_TXP0_224: BRK8310 (MC3.2), PCIE (C29.2)
MGT_TXP0_225: BRK8310 (MC3.22), PCIE (C19.2)
MGT_TXP1_224: BRK8310 (MC3.6), PCIE (C25.2)
MGT_TXP1_225: BRK8310 (MC3.26), PCIE (C17.2)
MGT_TXP2_224: BRK8310 (MC3.10), PCIE (C23.2)
MGT_TXP2_225: BRK8310 (MC3.30), PCIE (C15.2)
MGT_TXP3_224: BRK8310 (MC3.14), PCIE (C21.2)
MGT_TXP3_225: BRK8310 (MC3.34), PCIE (C13.2)
NetC11_2: BRK8310 (R1.1 R2.1), PCIE (C11.2 R20.2 U4.1)
PCIE_PERST_B_VIO: BRK8310 (R7.1 R8.1), PCIE (R12.2 R20.1 TP13.1 U4.3)
PCIE_SMCLK_VIO: BRK8310 (R11.1), PCIE (R14.1 TP12.1 U2.4)
PCIE_SMDAT_VIO: BRK8310 (R10.1), PCIE (R15.1 TP9.1 U2.3)
PCIE_WAKE_B_VIO: BRK8310 (R9.1), PCIE (R25.1 TP15.1 U6.3)

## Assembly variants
Default: not fitted C1 C2 C3 J2 MC4 MC5 MC6 MC7 MC8 MC9 MC10 MC11 R1 R5 R8 R12 R16 R17 R20 R21 R22 R26 R27 R28 U1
